// Mitsubishi GX Works2 project: PLC_MITSU_SAOTAMGIAC   PLC: FX1S

PROGRAM MAIN
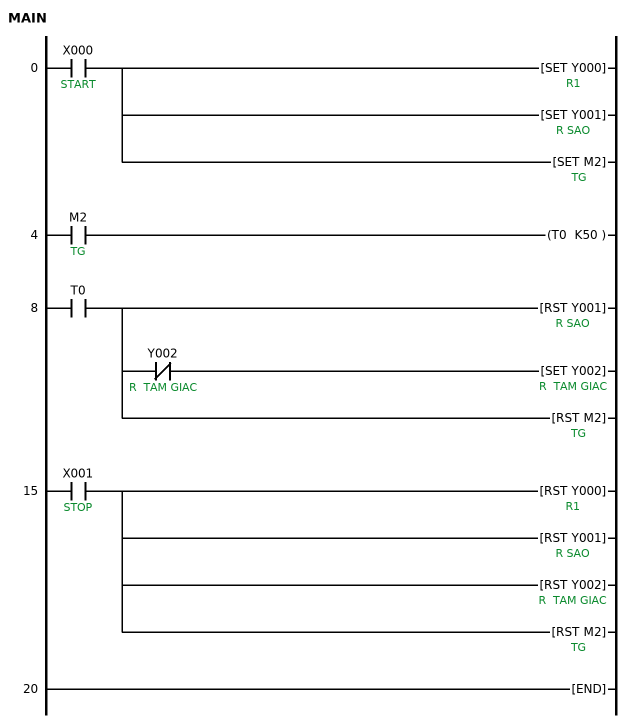
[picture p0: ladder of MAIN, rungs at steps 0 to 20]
0     LD      X000  ; START
      SET     Y000  ; R1
      SET     Y001  ; R SAO
      SET     M2  ; TG
4     LD      M2  ; TG
      OUT     T0 K50
8     LD      T0
      RST     Y001  ; R SAO
      MPS
      ANI     Y002  ; R  TAM GIAC
      SET     Y002  ; R  TAM GIAC
      MPP
      RST     M2  ; TG
15    LD      X001  ; STOP
      RST     Y000  ; R1
      RST     Y001  ; R SAO
      RST     Y002  ; R  TAM GIAC
      RST     M2  ; TG
20    END
END_PROGRAM
